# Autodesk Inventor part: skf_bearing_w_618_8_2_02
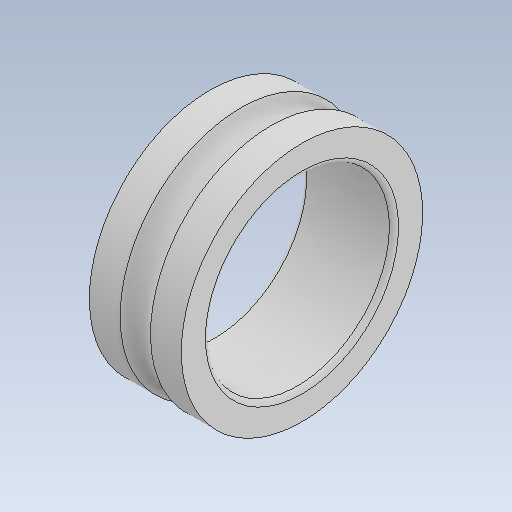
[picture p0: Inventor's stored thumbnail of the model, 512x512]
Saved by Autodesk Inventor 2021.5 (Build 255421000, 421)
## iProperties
Created: 2023-11
Part Number: skf_bearing_w_618_8_2_02
Checked By: TraceParts S.A.
Material: Generic
Catalog Web Link: www.traceparts.com
Document SubType Name: Modeling
Designer: TraceParts
Density: 1 g/cm^3
Appearance: Default
Company: TraceParts S.A.
Author: TraceParts
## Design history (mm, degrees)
feature "skf_bearing_w_618_8_2_02.ipt"
body "Solid1"
